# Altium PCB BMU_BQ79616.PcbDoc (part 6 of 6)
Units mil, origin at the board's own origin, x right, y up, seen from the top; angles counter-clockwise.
Board outline 7605 x 4005 mil, 4 copper layers (Top Layer, Layer 1, Layer 2, Bottom Layer), stack 37.446 mil thick; 709 components, 447 nets, 2028 pads, 1862 vias.
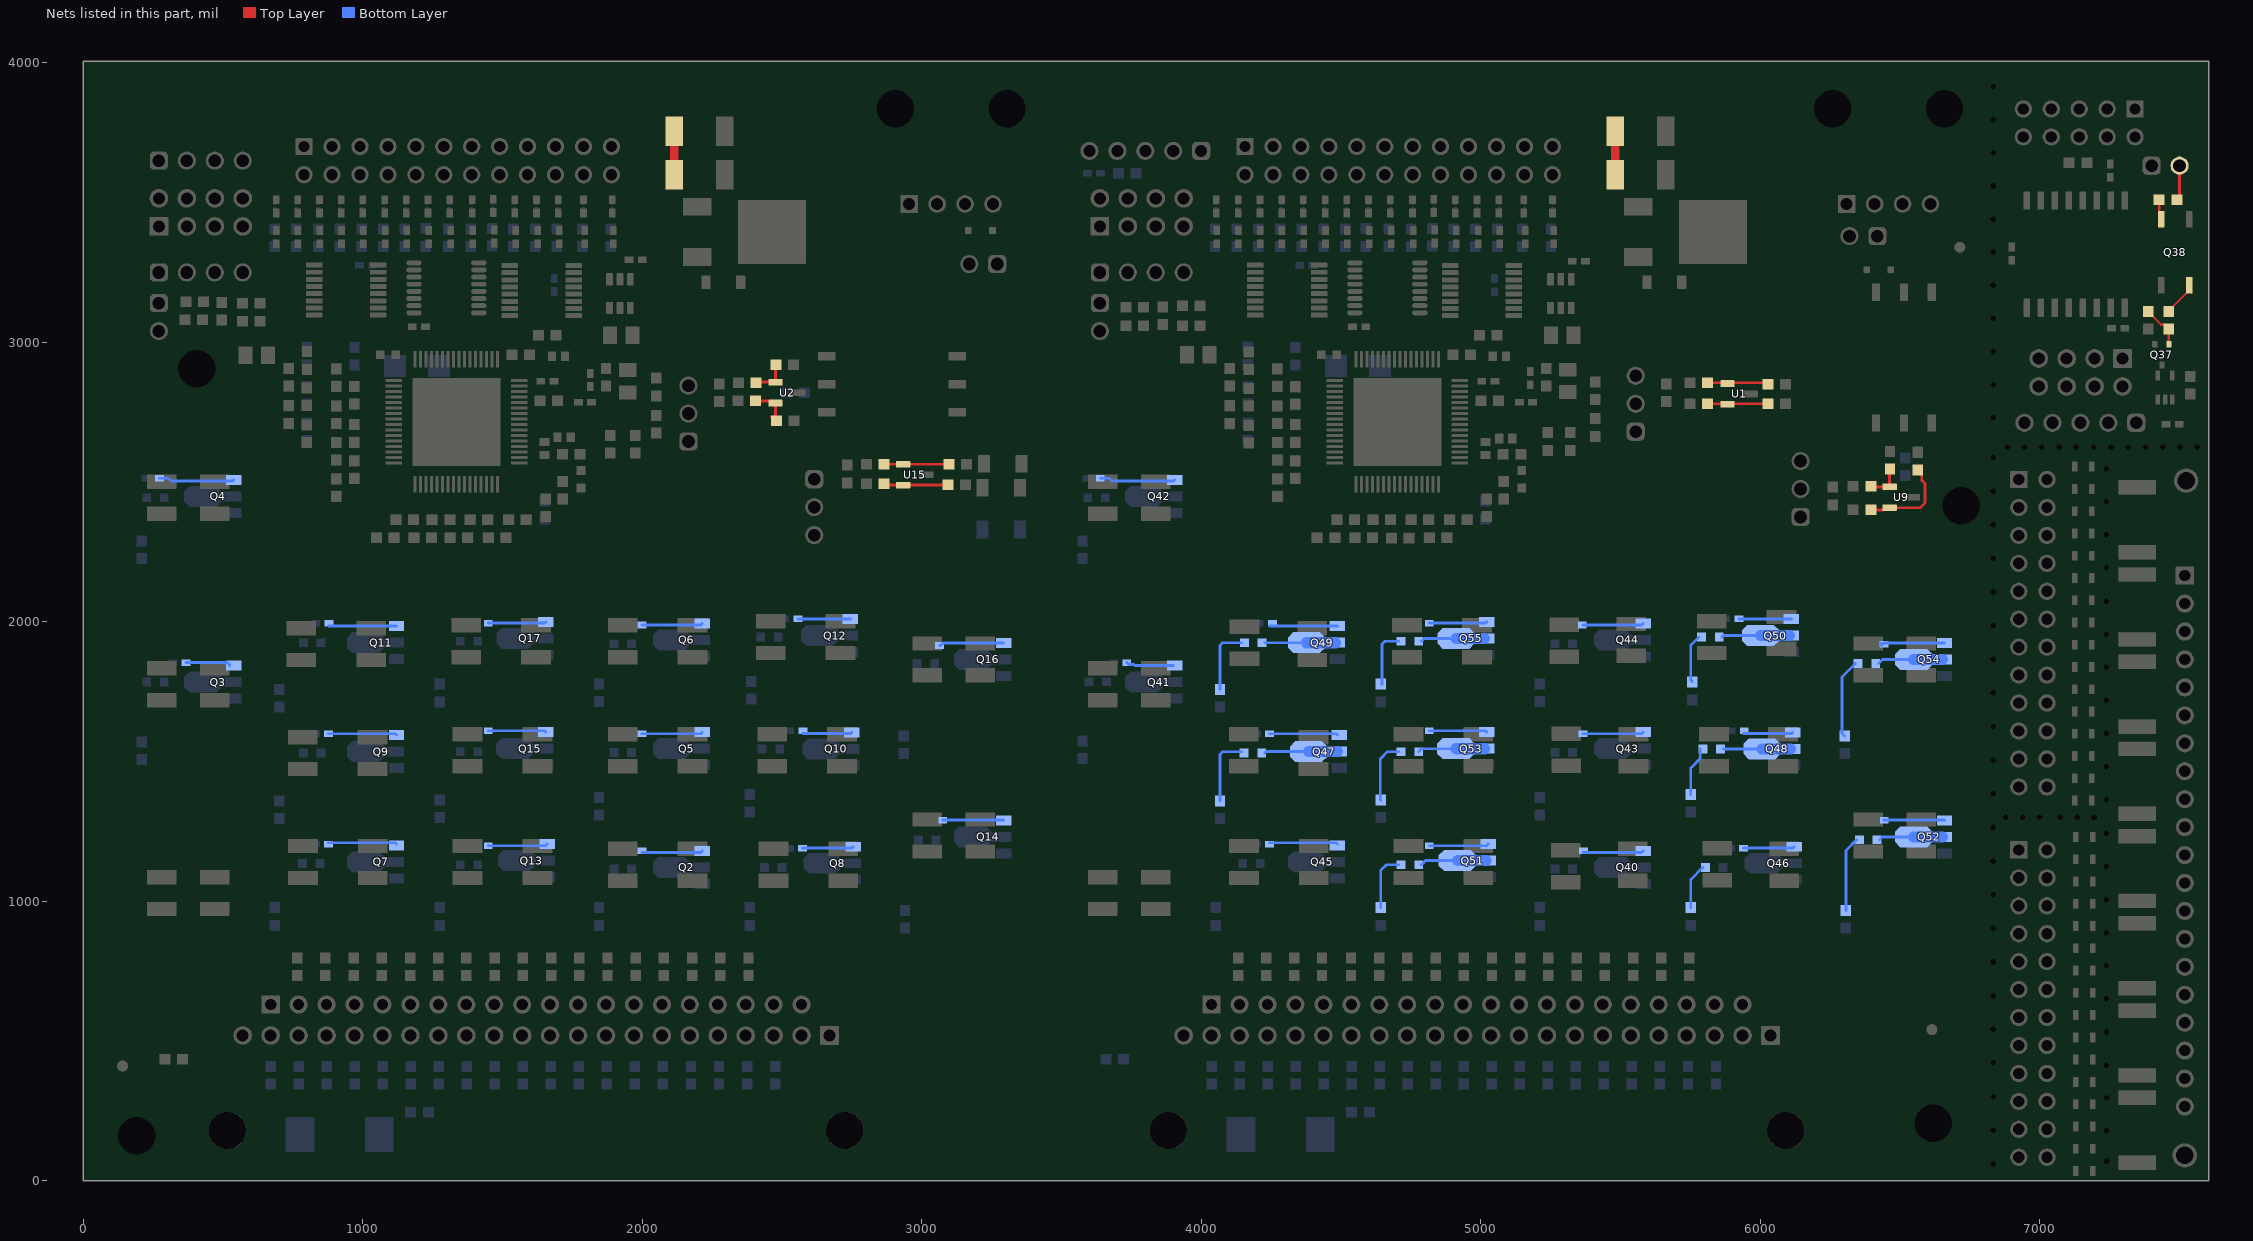
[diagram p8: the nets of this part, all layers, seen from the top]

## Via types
v1: diameter 20, hole 10, Top Layer to Bottom Layer, tented both sides, 1385 vias
v2: diameter 22.01, hole 12.01, Top Layer to Bottom Layer, tented both sides, 405 vias
v3: diameter 19.68, hole 7.87, Top Layer to Bottom Layer, 72 vias

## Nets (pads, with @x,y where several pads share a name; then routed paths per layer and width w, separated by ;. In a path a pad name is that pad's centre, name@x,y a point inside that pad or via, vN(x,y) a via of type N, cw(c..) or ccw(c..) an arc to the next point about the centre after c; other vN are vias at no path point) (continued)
NetD63_2: D63.2 R455.2 | length 161
  Bottom Layer w10: R455.2@5752.36,976.5 5752.36,1077.68 D63.2@5794.69,1120
NetD64_1: D64.1 Q47.2 Q47.4 | length 254.6
  Bottom Layer w10: D64.1@4227.36,1530 4232.76,1535.39 Q47.4@4377.36,1535.39
  Bottom Layer w40: Q47.4@4384.57,1535 Q47.2@4486.93,1535
NetD64_2: D64.2 R456.2 | length 248.5
  Bottom Layer w10: R456.2@4067.36,1357.99 4067.36,1525 4077.36,1535 D64.2@4144.69,1535
NetD65_1: D65.1 Q48.2 Q48.4 | length 240.6
  Bottom Layer w10: D65.1@5868.7,1545 Q48.4@6006.93,1545
  Bottom Layer w40: Q48.4@6006.93,1545 Q48.2@6109.29,1545
NetD65_2: D65.2 R465.2 | length 177.4
  Bottom Layer w10: R465.2@5752.36,1381.5 5752.36,1476.34 5786.02,1510 D65.2@5786.02,1545
NetD66_1: D66.1 Q49.2 Q49.4 | length 252.4
  Bottom Layer w10: D66.1@4227.36,1925 Q49.4@4377.36,1925
  Bottom Layer w40: Q49.4@4377.36,1925 Q49.2@4479.72,1925
NetD66_2: D66.2 R466.2 | length 238.5
  Bottom Layer w10: R466.2@4067.36,1757.99 4067.36,1915 4077.36,1925 D66.2@4144.69,1925
NetD67_1: D67.1 Q50.2 Q50.4 | length 242.9
  Bottom Layer w10: D67.1@5863.7,1945 5869.32,1950.62 Q50.4@6001.93,1950.62
  Bottom Layer w40: Q50.4@6001.93,1950.62 Q50.2@6104.29,1950.62
NetD67_2: D67.2 R475.2 | length 172.4
  Bottom Layer w10: R475.2@5757.36,1786.5 5752.36,1791.5 5752.36,1916.34 D67.2@5781.02,1945
NetD68_1: D68.1 Q51.2 Q51.4 | length 237.2
  Bottom Layer w10: D68.1@4788.42,1130 4803.82,1145.39 Q51.4@4916.93,1145.39
  Bottom Layer w40: Q51.4@4916.93,1145.39 Q51.2@5019.29,1145.39
NetD68_2: D68.2 R476.2 | length 205.2
  Bottom Layer w10: R476.2@4642.36,976.5 4642.36,1110 4662.36,1130 D68.2@4705.74,1130
NetD69_1: D69.1 Q52.2 Q52.4 | length 227.8
  Bottom Layer w10: D69.1@6428.7,1220 6438.7,1230 Q52.4@6550,1230
  Bottom Layer w40: Q52.4@6550,1230 Q52.2@6652.36,1230
NetD69_2: D69.2 R485.2 | length 269.5
  Bottom Layer w10: R485.2@6307.36,966.5 6307.43,966.56 6307.43,1181.4 D69.2@6346.02,1220
NetD70_1: D70.1 Q53.2 Q53.4 | length 239.7
  Bottom Layer w10: D70.1@4778.57,1535 4789.27,1545.69 Q53.4@4911.5,1545.69
  Bottom Layer w40: Q53.4@4911.5,1545.69 Q53.2@5013.86,1545.69
NetD70_2: D70.2 R486.2 | length 223.6
  Bottom Layer w10: R486.2@4642.36,1361.5 4640.74,1363.12 4640.74,1508.38 4667.36,1535 D70.2@4705.74,1535
NetD71_1: D71.1 Q54.2 Q54.4 | length 234.9
  Bottom Layer w10: D71.1@6423.7,1850 6438.7,1865 Q54.4@6550,1865
  Bottom Layer w40: Q54.4@6550,1865 Q54.2@6652.36,1865
NetD71_2: D71.2 R495.2 | length 281.9
  Bottom Layer w10: R495.2@6302.36,1591.5 6293.41,1600.44 6293.41,1802.39 D71.2@6341.02,1850
NetD72_1: D72.1 Q55.2 Q55.4 | length 230.2
  Bottom Layer w10: D72.1@4788.43,1930 4798.82,1940.39 Q55.4@4911.93,1940.39
  Bottom Layer w40: Q55.4@4911.93,1940.39 Q55.2@5014.29,1940.39
NetD72_2: D72.2 R496.2 | length 206
  Bottom Layer w10: R496.2@4647.36,1776.5 4647.36,1920 4657.36,1930 D72.2@4705.75,1930
NetJ5_2: J5.2 R142.1 | length 126
  Top Layer w8: J5.2@7501.24,3601.97 J5.2@7501.24,3631.97
  Top Layer w10: R142.1@7491.5,3510 7501.24,3519.74 J5.2@7501.24,3601.97
NetQ2_1: Q2.1 R12.2 | length 218.6
  Bottom Layer w10: R12.2@1998.62,1173.77 2208.9,1173.77 Q2.1@2214.8,1179.68
NetQ3_1: Q3.1 R13.2 | length 161.9
  Bottom Layer w10: R13.2@366.57,1853.75 515.19,1853.75 523.15,1845.8 Q3.1@523.15,1843.75
NetQ4_1: Q4.1 R16.2 | length 272
  Bottom Layer w10: R16.2@271.57,2513.75 302.95,2513.75 312.95,2503.75 533.7,2503.75 Q4.1@537.75,2507.81
NetQ5_1: Q5.1 R17.2 | length 218.6
  Bottom Layer w10: R17.2@1998.62,1598.77 2208.9,1598.77 Q5.1@2214.8,1604.68
NetQ6_1: Q6.1 R20.2 | length 218.6
  Bottom Layer w10: R20.2@1998.62,1988.15 2208.9,1988.15 Q6.1@2214.8,1994.06
NetQ7_1: Q7.1 R95.2 | length 244.6
  Bottom Layer w10: R95.2@877.4,1208.76 1115.92,1208.76 Q7.1@1120.24,1204.45
NetQ8_1: Q8.1 R106.2 | length 183.1
  Bottom Layer w10: R106.2@2573.62,1190 2750.13,1190 Q8.1@2754.8,1194.68
NetQ9_1: Q9.1 R107.2 | length 244.6
  Bottom Layer w10: R107.2@877.4,1598.76 1115.92,1598.76 Q9.1@1120.24,1594.45
NetQ10_1: Q10.1 R123.2 | length 177.9
  Bottom Layer w10: R123.2@2573.62,1600 2745.75,1600 Q10.1@2749.8,1604.06
NetQ11_1: Q11.1 R124.2 | length 243.2
  Bottom Layer w10: R124.2@877.4,1985 1119.29,1985 Q11.1@1120.24,1984.06
NetQ12_1: Q12.1 R134.2 | length 187.7
  Bottom Layer w10: R134.2@2557.24,2010 2744.48,2010 Q12.1@2744.8,2009.68
NetQ13_1: Q13.1 R135.2 | length 213.6
  Bottom Layer w10: R135.2@1448.62,1198.54 1653.9,1198.54 Q13.1@1659.8,1204.45
NetQ14_1: Q14.1 R136.2 | length 218.3
  Bottom Layer w10: R136.2@3075,1290 3291.93,1290 Q14.1@3292.87,1289.06
NetQ15_1: Q15.1 R137.2 | length 207.9
  Bottom Layer w10: R137.2@1448.62,1610 1649.12,1610 Q15.1@1654.37,1604.75
NetQ16_1: Q16.1 R138.2 | length 233
  Bottom Layer w10: R138.2@3063.62,1915 3067.56,1915 3076.61,1924.06 Q16.1@3292.87,1924.06
NetQ17_1: Q17.1 R139.2 | length 208
  Bottom Layer w10: R139.2@1448.62,1995 1650.35,1995 Q17.1@1654.8,1999.45
NetQ37_1: Q37.1 R140.2 R141.1 | length 152.6
  Top Layer w8: R140.2@7389.24,3110.46 7389.24,3109.48 7435.56,3063.16 7447.54,3063.16 7462.24,3048.46 R141.1@7462.24,3047.47 7462.83,3046.88 Q37.1@7462.83,2995.37
NetQ38_2: Q38.2 R142.2 | length 72.5
  Top Layer w10: R142.2@7428.5,3510 7428.5,3465.77 7435.95,3458.33 Q38.2@7435.95,3440.61
NetQ38_4: Q38.4 R141.2 | length 135.5
  Top Layer w8: R141.2@7462.24,3110.46 7476.94,3125.17 7476.94,3127.67 Q38.4@7535.95,3186.67 ; Q38.4@7535.95,3204.39 Q38.4@7535.95,3186.67 ; Q38.4@7543.76,3178.86 Q38.4@7535.95,3186.67
NetQ40_1: Q40.1 R427.2 | length 218.6
  Bottom Layer w10: R427.2@5365.98,1173.77 5576.26,1173.77 Q40.1@5582.17,1179.68
NetQ41_1: Q41.1 R428.2 | length 170.6
  Bottom Layer w10: R428.2@3733.93,1853.75 3740.26,1847.43 3758.98,1847.43 3762.66,1843.75 3899.56,1843.75 Q41.1@3900.11,1843.2
NetQ42_1: Q42.1 R437.2 | length 272
  Bottom Layer w10: R437.2@3638.93,2513.75 3670.31,2513.75 3680.31,2503.75 3901.06,2503.75 Q42.1@3905.11,2507.81
NetQ43_1: Q43.1 R438.2 | length 218.6
  Bottom Layer w10: R438.2@5365.98,1598.77 5576.26,1598.77 Q43.1@5582.17,1604.68
NetQ44_1: Q44.1 R447.2 | length 218.6
  Bottom Layer w10: R447.2@5365.98,1988.15 5576.26,1988.15 Q44.1@5582.17,1994.06
NetQ45_1: Q45.1 R448.2 | length 244.6
  Bottom Layer w10: R448.2@4244.76,1208.76 4483.28,1208.76 Q45.1@4487.6,1204.45
NetQ46_1: Q46.1 R457.2 | length 183.1
  Bottom Layer w10: R457.2@5940.98,1190 6117.49,1190 Q46.1@6122.17,1194.68
NetQ47_1: Q47.1 R458.2 | length 244.6
  Bottom Layer w10: R458.2@4244.76,1598.76 4483.28,1598.76 Q47.1@4487.6,1594.45
NetQ48_1: Q48.1 R467.2 | length 177.9
  Bottom Layer w10: R467.2@5940.98,1600 6113.11,1600 Q48.1@6117.17,1604.06
NetQ49_1: Q49.1 R468.2 | length 243.2
  Bottom Layer w10: R468.2@4244.76,1985 4486.65,1985 Q49.1@4487.6,1984.06
NetQ50_1: Q50.1 R477.2 | length 187.7
  Bottom Layer w10: R477.2@5924.61,2010 6111.84,2010 Q50.1@6112.17,2009.68
NetQ51_1: Q51.1 R478.2 | length 213.6
  Bottom Layer w10: R478.2@4815.98,1198.54 5021.26,1198.54 Q51.1@5027.17,1204.45
NetQ52_1: Q52.1 R487.2 | length 218.3
  Bottom Layer w10: R487.2@6442.36,1290 6659.29,1290 Q52.1@6660.24,1289.06
NetQ53_1: Q53.1 R488.2 | length 207.9
  Bottom Layer w10: R488.2@4815.98,1610 5016.48,1610 Q53.1@5021.73,1604.75
NetQ54_1: Q54.1 R497.2 | length 233
  Bottom Layer w10: R497.2@6433.78,1922.76 R497.2@6437.72,1922.76 ; R497.2@6434.92,1915 6443.98,1924.06 Q54.1@6660.24,1924.06
NetQ55_1: Q55.1 R498.2 | length 208
  Bottom Layer w10: R498.2@4815.98,1995 5017.72,1995 Q55.1@5022.17,1999.45
NetR24_2: R24.2 R25.1 | length 145
  Top Layer w30: R24.2@2114.45,3600 R25.1@2114.45,3745
NetR69_1: R69.1 R70.2 U15.2 | length 231.1
  Top Layer w10: R69.1@2864.84,2493.7 2869.65,2488.9 U15.2@2933.35,2488.9 3092.4,2488.9 R70.2@3093.5,2490
NetR71_1: R71.1 R72.2 U1.1 | length 219.1
  Top Layer w10: R72.2@5811.5,2855 6023.5,2855 R71.1@6028.5,2850
NetR75_1: R75.1 R76.2 U15.1 | length 232
  Top Layer w10: R75.1@2864.84,2563.7 U15.1@2933.35,2563.7 R76.2@3096.85,2563.7
NetR77_1: R77.1 R78.2 U1.2 | length 217
  Top Layer w10: R78.2@5811.5,2780 R77.1@6028.5,2780
NetR80_2: R80.2 R81.1 U9.1 | length 153.8
  Top Layer w10: R81.1@6410.2,2498.7 R81.1@6396.5,2485 6399.09,2482.4 U9.1@6463.66,2482.4 6463.66,2545.67 R80.2@6465,2547.01 R80.2@6465,2546.02
NetR82_2: R82.2 R83.1 U2.1 | length 135.5
  Top Layer w10: R82.2@2407.48,2855 R82.2@2406.5,2855 2408.9,2857.4 U2.1@2476.57,2857.4 2476.57,2918.07 R83.1@2478.5,2920
NetR88_2: R88.2 R89.1 U9.2 | length 332.7
  Top Layer w10: R89.1@6396.5,2400 6442.28,2400 6449.88,2407.6 U9.2@6463.66,2407.6 6572.6,2407.6 6590,2425 6590,2495 6578.7,2506.3 6578.7,2529.8 R88.2@6565,2543.5
NetR90_2: R90.2 R91.1 U2.2 | length 157.8
  Top Layer w10: R90.2@2404.68,2790 2405.67,2790 2455.39,2790 2462.8,2782.6 U2.2@2476.57,2782.6 R91.1@2476.57,2723.43 ; R91.1@2461.97,2733.7 2466.3,2733.7 R91.1@2476.57,2723.43 ; R91.1@2480,2720 R91.1@2476.57,2723.43
NetR151_2: R151.2 R152.1 | length 145
  Top Layer w30: R151.2@5481.81,3600 R152.1@5481.81,3745
pads on no net: FID1.1 FID2.1 FID3.1 FID4.1 FID5.1 FID6.1 J4.20 J10. J10.1 J10.2 J10.22 J12.1 J12.2 J12.4 J12.9 J12.10 J15.20 J18.20 J21. J21.1 J21.2 J21.22 J30.3 J30.4 J30.MH1 J30.MH2 J31.1 J31.2 J31.MH1 J31.MH2 LBL1.0 T1.5 T2.2 U3.4 U3.5 U7.7 U8.7 U17.14 U18.4 U18.5 U22.7 U23.7

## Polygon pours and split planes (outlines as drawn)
A1_GND on Top Layer "A1_GND_L01_P008" (solid, remove dead copper, pour order 8): 3435,3994.98 3435,-10 6810,-10 6810,3989.86
A2_GND on Top Layer "A2_GND_L01_P031" (solid, remove dead copper, pour order 31): 1.94,4005 1.94,0 3391.94,0 3391.94,3999.86
A2_GND on Top Layer "A2_GND_L01_P000" (solid, remove dead copper, pour order 0): 0,4005 0,0 3390,0 3390,3999.86
A1_GND_ISO on Top Layer "A1_GND_ISO_L01_P012" (solid, remove dead copper, pour order 12): 6865,4000 6865,3485 6885,3485 6980,3485 7605,3485 7605,4000
A0_GND on Top Layer "A0_GND_L01_P013" (solid, remove dead copper, pour order 13): 6860,3160 6860,2645 6880,2645 6975,2645 7600,2645 7600,3160
NetC3_2 on Top Layer "NETC3_2_L01_P020" (solid, remove dead copper, pour order 20): 2246.75,3064.24 2744.24,3064.24 2745,3065 2744.28,3065.72 2744.28,3854.96 2253.5,3854.96
NetC154_2 on Top Layer "NETC154_2_L01_P029" (solid, remove dead copper, pour order 29): 5616.08,3064.24 6113.57,3064.24 6114.33,3065 6113.61,3065.72 6113.61,3854.96 5622.83,3854.96
A2_GND on Layer 2 "A2_GND_L03_P006" (solid, remove dead copper, pour order 6): 0,4005 0,0 3365,0 3365,3999.89
A1_GND on Layer 2 "A1_GND_L03_P010" (solid, remove dead copper, pour order 10): 3435,3994.98 3435,-10 6810,-10 6810,3989.86
A0_GND on Layer 2 "A0_GND_L03_P015" (solid, pour order 15): 6860,3160 6860,2645 6880,2645 6975,2645 7600,2645 7600,3160
A1_GND_ISO on Layer 2 "A1_GND_ISO_L03_P018" (solid, pour order 18): 6865,4000 6865,3485 6885,3485 6980,3485 7605,3485 7605,4000
NetC154_2 on Layer 2 "NETC154_2_L03_P023" (solid, pour order 23): 5616.08,3064.24 6113.57,3064.24 6114.33,3065 6113.61,3065.72 6113.61,3854.96 5622.83,3854.96
NetC3_2 on Layer 2 "NETC3_2_L03_P027" (solid, pour order 27): 2246.75,3064.24 2744.24,3064.24 2745,3065 2744.28,3065.72 2744.28,3854.96 2253.5,3854.96
A2_GND on Layer 1 "A2_GND_L02_P005" (solid, remove dead copper, pour order 5): 0,4005 0,0 3365,0 3365,3999.89
A1_GND on Layer 1 "A1_GND_L02_P009" (solid, remove dead copper, pour order 9): 3435,3994.98 3435,-10 6810,-10 6810,3989.86
A0_GND on Layer 1 "A0_GND_L02_P014" (solid, remove dead copper, pour order 14): 6860,3160 6860,2645 6880,2645 6975,2645 7600,2645 7600,3160
A1_GND_ISO on Layer 1 "A1_GND_ISO_L02_P017" (solid, remove dead copper, pour order 17): 6865,4000 6865,3485 6885,3485 6980,3485 7605,3485 7605,4000
NetC154_2 on Layer 1 "NETC154_2_L02_P024" (solid, remove dead copper, pour order 24): 5616.08,3064.24 6113.57,3064.24 6114.33,3065 6113.61,3065.72 6113.61,3854.96 5622.83,3854.96
NetC3_2 on Layer 1 "NETC3_2_L02_P026" (solid, remove dead copper, pour order 26): 2246.75,3064.24 2744.24,3064.24 2745,3065 2744.28,3065.72 2744.28,3854.96 2253.5,3854.96
A1M_CELL0S on Layer 1 "A1M_CELL0S_L02_P030" (solid, pour order 30): 6860,2625 6870,2615 6870,0 7605,0 7605,2625
A2_GND on Bottom Layer "A2_GND_L04_P007" (solid, remove dead copper, pour order 7): 0,4005 0,0 3390,0 3390,3999.86
A1_GND on Bottom Layer "A1_GND_L04_P011" (solid, remove dead copper, pour order 11): 3435,3994.98 3435,-10 6810,-10 6810,3989.86
A0_GND on Bottom Layer "A0_GND_L04_P016" (solid, remove dead copper, pour order 16): 6860,3160 6860,2645 6880,2645 6975,2645 7600,2645 7600,3160
A1_GND_ISO on Bottom Layer "A1_GND_ISO_L04_P019" (solid, remove dead copper, pour order 19): 6865,4000 6865,3485 6885,3485 6980,3485 7605,3485 7605,4000
NetC154_2 on Bottom Layer "NETC154_2_L04_P025" (solid, remove dead copper, pour order 25): 5616.08,3064.24 6113.57,3064.24 6114.33,3065 6113.61,3065.72 6113.61,3854.96 5622.83,3854.96
NetC3_2 on Bottom Layer "NETC3_2_L04_P028" (solid, remove dead copper, pour order 28): 2246.75,3064.24 2744.24,3064.24 2745,3065 2744.28,3065.72 2744.28,3854.96 2253.5,3854.96

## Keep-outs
Keep-Out Layer:
  text ".Layer_Name" at 577,-858.49 h60

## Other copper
Top Layer:
  pour cut-out: 2030,2680 2000,2710 2000,2735 1985,2735 1995,2725 1995,2710 2015,2690 2015,2515 2030,2515
  pour cut-out: 2550,2975 2165.21,2975 2005,2814.79 2005,2705 2075,2635 2305,2635 2615,2635 2615,2975
  pour cut-out: 4039.92,3532.17 5394.92,3532.17 5394.92,3028.78 4039.92,3028.78
  pour cut-out: 670,3536.69 2025,3536.69 2025,3033.31 670,3033.31
  pour cut-out: 2560,2655 2560,2275 3205.18,2275 3235,2317.6 3235,2655
  pour cut-out: 6865,3595 7600,3595 7600,3060 7605,3055 6860,3055
  pour cut-out: 1517.64,2898.18 1517.64,2525 1147.64,2525 1142.64,2530 1142.64,2898.18 1517.64,2898.18 1492.64,2875 1177.64,2875 1167.64,2865 1167.64,2540 1487.64,2540 1492.64,2545 1492.64,2875
  pour cut-out: 2260,3518.31 2035,3518.31 2035,3803.31 2260,3803.31
  pour cut-out: 115,3935 60,3880 60,95 105,50 215,50 215,3790 230,3805 2820,3805 2820,3935
  pour cut-out: 5605,3502.5 5380,3502.5 5380,3787.5 5605,3787.5
  pour cut-out: 75,2750.25 75,3017.5 1170,3017.5 1170,2547.88 1483.71,2547.88 1623.03,2408.56 1623.03,2364.25 1623.03,2270 831.59,2270 699.09,2402.5 699.09,2750.25
  region net A2_BAT: 980,2963.64 1047.64,2970 1047.64,2940 1012.26,2931.38 998.63,2945 980,2945
  region net A1_BAT: 4347.36,2963.64 4415,2970 4415,2940 4379.62,2931.38 4366,2945 4347.36,2945
  pour cut-out: 3410,2740.9 3410,3008.15 4547.87,3008.15 4547.87,2538.53 4861.58,2538.53 5000.9,2399.21 5000.9,2354.9 5000.9,2260.65 4209.46,2260.65 4076.96,2393.15 4076.96,2740.9
  pour cut-out: 3574.98,385.01 3580,379.99 3580,0 3420,0 3422.89,2.89 3422.89,363.21
  pour cut-out: 5975,2965 5925,2965 5485,2965 5480,2960 5450,2960 5437.2,2947.2 5437.2,2637.8 5450,2625 5680,2625 6170,2625 6170,2965
  pour cut-out: 3540,3815 3495,3770 3495,2495 3420,2420 3300,2420 3300,2625 3295,2630 3320,2655 3335,2655 3335,3790 3355,3810 3355,3850 3410,3905 3425,3905
  pour cut-out: 3425,3940 6195,3940 6195,3790 3425,3790 3425,3860
  pour cut-out: 4885,2898.18 4885,2525 4515,2525 4510,2530 4510,2898.18 4885,2898.18 4860,2875 4545,2875 4535,2865 4535,2540 4855,2540 4860,2545 4860,2875
  pour cut-out: 197.71,820 2780,820 2780,345.87 193.2,345.87
  pour cut-out: 3427.33,830 6148.85,830 6148.85,363.21 3422.89,363.21
  region net A1_CB15: 3549.43,2110 3549.43,1788.41 3949.43,1788.41 3949.43,2110
  pour cut-out: 6600,2655 6550,2655 6110,2655 6105,2650 6095,2650 6095,2315 6305,2315 6825,2315 6825,2655
  pour cut-out: 5210,2554.18 5223.29,2554.18 5223.29,2476.71 5305,2395 6091.63,2395 6095,2398.37 6095,2385 5300,2385 5210,2475
  pour cut-out: 5380,2625 5390,2625 5390,2535 5405,2520 6095,2520 6090,2515 6090,2510 5395,2510 5380,2525
  pour cut-out: 1995,2400 1920,2400 1885,2435 1885,2560 1855,2560 1840,2560 1840,2550 1875,2550 1875,2430 1915,2390 1995,2390
  pour cut-out: 1995,2390 2555,2390 2635,2390 2635,2400 1995,2400
  pour cut-out: 2015,2505 2550,2505 2555,2505 2625,2570 2630,2570 2630,2585 2625,2590 2550,2515 2015,2515
  region net A2_CB14: 182.07,2750 182.07,2463.41 582.07,2463.41 582.07,2750
  region net A1_CB14: 3549.43,2750 3549.43,2463.41 3949.43,2463.41 3949.43,2750
  region net A1_CB4: 5722.36,1326.39 5722.36,1146.39 6210.68,1146.39 6210.68,1326.39
  region net A1_CB7: 5167.36,1325 5167.36,1145 5647.36,1145 5647.36,1325
  region net A1_CELL4: 5722.36,1120.8 5722.36,940.8 6212.44,940.8 6212.44,1120.8
  region net A1_CELL3: 5727.36,1532.05 5727.36,1352.05 6208.28,1352.05 6208.28,1532.05
  region net A1_CELL6: 5172.36,1530.66 5172.36,1350.66 5649.97,1350.66 5649.97,1530.66
  region net A1_CELL7: 5167.36,1119.4 5167.36,939.4 5649.12,939.4 5649.12,1119.4
  region net A1_CELL10: 4589.12,1124.4 4589.12,944.4 5097.36,944.4 5097.36,1124.4
  region net A1_CB10: 4587.36,1330 4587.36,1150 5097.36,1150 5097.36,1330
  region net A1_CELL9: 4589.97,1525.66 4589.97,1345.66 5097.36,1345.66 5097.36,1525.66
  region net A1_CELL1: 6287.36,1218.1 6287.36,885 6690.63,885 6690.63,1218.1
  region net A1_CB1: 6292.36,1560 6292.36,1264.93 6692.36,1264.93 6692.36,1560
  region net A1_CB13: 4018.39,1325 4018.39,1145 4517.36,1145 4517.36,1325
  region net A1_CELL13: 4020.15,1119.4 4020.15,939.4 4517.36,939.4 4517.36,1119.4
  region net A1_CELL12: 4019.97,1515.66 4019.97,1335.66 4522.36,1335.66 4522.36,1515.66
  region net A1_CB2: 5717.36,2152.65 5717.36,1972.65 6206.53,1972.65 6206.53,2152.65
  region net A1_CB5: 5172.36,2136.25 5172.36,1956.25 5647.36,1956.25 5647.36,2136.25
  region net A1_CB0: 6282.36,2195 6282.36,1884.69 6692.26,1884.69 6692.26,2195
  region net A1_CELL0S: 6287.36,1837.86 6287.36,1572.79 6690.52,1572.79 6690.52,1837.86
  region net A1_CELL2: 5717.36,1947.05 5717.36,1767.05 6208.28,1767.05 6208.28,1947.05
  region net A1_CB3: 5717.36,1737.65 5717.36,1557.65 6206.53,1557.65 6206.53,1737.65
  region net A1_CELL14: 3549.43,2438.48 3549.43,2125 3949.43,2125 3949.43,2438.48
  region net A1_CB8: 4588.21,2131.25 4588.21,1951.25 5092.36,1951.25 5092.36,2131.25
  region net A1_CELL11: 4019.97,1915.66 4019.97,1735.66 4517.36,1735.66 4517.36,1915.66
  region net A1_CELL8: 4589.97,1925.66 4589.97,1745.66 5092.36,1745.66 5092.36,1925.66
  region net A1_CB12: 4018.21,1721.25 4018.21,1541.25 4522.36,1541.25 4522.36,1721.25
  region net A1_CB9: 4588.21,1731.25 4588.21,1551.25 5097.36,1551.25 5097.36,1731.25
  region net A1_CELL5: 5172.36,1930.66 5172.36,1750.66 5647.36,1750.66 5647.36,1930.66
  region net A1_CB6: 5172.36,1736.25 5172.36,1556.25 5648.21,1556.25 5648.21,1736.25
  region net A1_CB16: 3547.36,1405 3547.36,1033.68 3940.31,1033.68 3940.31,1405
  region net A1_CELL16S: 3547.36,1008.75 3547.36,655 3940.31,655 3940.31,1008.75
  region net A1_CELL15: 3549.43,1763.48 3549.43,1425 3949.43,1425 3949.43,1763.48
  region net A1_CB11: 4018.21,2121.25 4018.21,1941.25 4517.36,1941.25 4517.36,2121.25
  region net A2_CB5: 1805,2136.25 1805,1956.25 2280,1956.25 2280,2136.25
  region net A2_CELL5: 1805,1930.66 1805,1750.66 2280,1750.66 2280,1930.66
  region net A2_CB6: 1805,1736.25 1805,1556.25 2280.85,1556.25 2280.85,1736.25
  region net A2_CELL6: 1805,1530.66 1805,1350.66 2282.6,1350.66 2282.6,1530.66
  region net A2_CELL11: 652.6,1915.66 652.6,1735.66 1150,1735.66 1150,1915.66
  region net A2_CB11: 650.85,2121.25 650.85,1941.25 1150,1941.25 1150,2121.25
  region net A2_CELL2: 2350,1947.05 2350,1767.05 2840.92,1767.05 2840.92,1947.05
  region net A2_CB2: 2350,2152.65 2350,1972.65 2839.16,1972.65 2839.16,2152.65
  region net A2_CELL0S: 2920,1837.86 2920,1572.79 3323.16,1572.79 3323.16,1837.86
  region net A2_CELL4: 2355,1120.8 2355,940.8 2845.08,940.8 2845.08,1120.8
  region net A2_CB3: 2350,1737.65 2350,1557.65 2839.16,1557.65 2839.16,1737.65
  region net A2_CELL3: 2360,1532.05 2360,1352.05 2840.92,1352.05 2840.92,1532.05
  region net A2_CB4: 2355,1326.39 2355,1146.39 2843.32,1146.39 2843.32,1326.39
  region net A2_CELL10: 1221.76,1124.4 1221.76,944.4 1730,944.4 1730,1124.4
  region net A2_CELL9: 1222.6,1525.66 1222.6,1345.66 1730,1345.66 1730,1525.66
  region net A2_CB8: 1220.85,2131.25 1220.85,1951.25 1725,1951.25 1725,2131.25
  region net A2_CELL8: 1222.6,1925.66 1222.6,1745.66 1725,1745.66 1725,1925.66
  region net A2_CB9: 1220.85,1731.25 1220.85,1551.25 1730,1551.25 1730,1731.25
  region net A2_CB12: 650.85,1721.25 650.85,1541.25 1155,1541.25 1155,1721.25
  region net A2_CELL12: 652.6,1515.66 652.6,1335.66 1155,1335.66 1155,1515.66
  region net A2_CB13: 651.03,1325 651.03,1145 1150,1145 1150,1325
  region net A2_CB10: 1220,1330 1220,1150 1730,1150 1730,1330
  region net A2_CELL13: 653.01,1095.63 653.01,915.63 1150.22,915.63 1150.22,1095.63
  region net A2_CB7: 1800,1325 1800,1145 2280,1145 2280,1325
  region net A2_CELL7: 1800,1119.4 1800,939.4 2281.76,939.4 2281.76,1119.4
  region net A2_CELL15: 182.07,1763.48 182.07,1425 582.07,1425 582.07,1763.48
  region net A2_CB15: 182.07,2110 182.07,1788.41 582.07,1788.41 582.07,2110
  region net A2_CELL16S: 180,1008.75 180,655 572.95,655 572.95,1008.75
  region net A2_CB16: 180,1405 180,1033.68 572.95,1033.68 572.95,1405
  region net A2_CELL14: 182.07,2438.48 182.07,2125 582.07,2125 582.07,2438.48
  region net A2_CB1: 2925,1560 2925,1264.93 3325,1264.93 3325,1560
  region net A2_CELL1: 2920,1218.1 2920,885 3323.26,885 3323.26,1218.1
  region net A2_CB0: 2915,2195 2915,1884.69 3324.9,1884.69 3324.9,2195
  region net A2_CB0: 2915,2195 2915,1884.69 3324.9,1884.69 3324.9,2195
  region net A2_CELL1: 2920,1218.1 2920,885 3323.26,885 3323.26,1218.1
  region net A2_CB1: 2925,1560 2925,1264.93 3325,1264.93 3325,1560
  region net A2_CELL14: 182.07,2438.48 182.07,2125 582.07,2125 582.07,2438.48
  region net A2_CB14: 182.07,2750 182.07,2463.41 582.07,2463.41 582.07,2750
  region net A2_CB16: 180,1405 180,1033.68 572.95,1033.68 572.95,1405
  region net A2_CELL16S: 180,1008.75 180,655 572.95,655 572.95,1008.75
  region net A2_CB15: 182.07,2110 182.07,1788.41 582.07,1788.41 582.07,2110
  region net A2_CELL15: 182.07,1763.48 182.07,1425 582.07,1425 582.07,1763.48
  region net A2_CELL7: 1800,1119.4 1800,939.4 2281.76,939.4 2281.76,1119.4
  region net A2_CB7: 1800,1325 1800,1145 2280,1145 2280,1325
  region net A2_CELL13: 652.79,1119.4 652.79,939.4 1150,939.4 1150,1119.4
  region net A2_CB10: 1220,1330 1220,1150 1730,1150 1730,1330
  region net A2_CB13: 651.03,1325 651.03,1145 1150,1145 1150,1325
  region net A2_CELL12: 652.6,1515.66 652.6,1335.66 1155,1335.66 1155,1515.66
  region net A2_CB12: 650.85,1721.25 650.85,1541.25 1155,1541.25 1155,1721.25
  region net A2_CB9: 1220.85,1731.25 1220.85,1551.25 1730,1551.25 1730,1731.25
  region net A2_CELL8: 1222.6,1925.66 1222.6,1745.66 1725,1745.66 1725,1925.66
  region net A2_CB8: 1220.85,2131.25 1220.85,1951.25 1725,1951.25 1725,2131.25
  region net A2_CELL9: 1222.6,1525.66 1222.6,1345.66 1730,1345.66 1730,1525.66
  region net A2_CELL10: 1221.76,1124.4 1221.76,944.4 1730,944.4 1730,1124.4
  region net A2_CB4: 2355,1326.39 2355,1146.39 2843.32,1146.39 2843.32,1326.39
  region net A2_CELL3: 2360,1532.05 2360,1352.05 2840.92,1352.05 2840.92,1532.05
  region net A2_CB3: 2350,1737.65 2350,1557.65 2839.16,1557.65 2839.16,1737.65
  region net A2_CELL4: 2355,1120.8 2355,940.8 2845.08,940.8 2845.08,1120.8
  region net A2_CELL0S: 2920,1837.86 2920,1572.79 3323.16,1572.79 3323.16,1837.86
  region net A2_CB2: 2350,2152.65 2350,1972.65 2839.16,1972.65 2839.16,2152.65
  region net A2_CELL2: 2350,1947.05 2350,1767.05 2840.92,1767.05 2840.92,1947.05
  region net A2_CB11: 650.85,2121.25 650.85,1941.25 1150,1941.25 1150,2121.25
  region net A2_CELL11: 652.6,1915.66 652.6,1735.66 1150,1735.66 1150,1915.66
  region net A2_CELL6: 1805,1530.66 1805,1350.66 2282.6,1350.66 2282.6,1530.66
  region net A2_CB6: 1805,1736.25 1805,1556.25 2280.85,1556.25 2280.85,1736.25
  region net A2_CELL5: 1805,1930.66 1805,1750.66 2280,1750.66 2280,1930.66
  region net A2_CB5: 1805,2136.25 1805,1956.25 2280,1956.25 2280,2136.25
  text ".Layer_Name" at 577,-858.49 h60
Layer 1:
  pour cut-out: 5347.36,2785 5337.36,2775 4882.36,2775 4882.36,2780 4912.36,2780 5329.76,2780 5347.36,2797.6
  pour cut-out: 5347.36,2797.6 5347.36,2785 5492.36,2930 5922.36,2930 6187.36,3195 6187.36,3940 5487.44,3940 5488.92,3005 4834.88,3005 4819.86,2989.99 4819.86,2890 4822.36,2890 4822.36,2945 4822.36,2981.91 4839.86,2997.5 5349.86,2997.5 5503.09,2997.5 5501.59,3925 6167.36,3925 6167.36,3200 5912.36,2945 5489.02,2945
  pour cut-out: 1980,2797.6 1980,2785 2125,2930 2555,2930 2820,3195 2820,3940 2120.07,3940 2121.56,3005 1467.51,3005 1452.5,2989.99 1452.5,2890 1455,2890 1455,2945 1455,2981.91 1472.5,2997.5 1982.5,2997.5 2135.72,2997.5 2134.22,3925 2800,3925 2800,3200 2545,2945 2121.66,2945
  pour cut-out: 4882.36,2700 5197.36,2700 5197.36,2615 5207.36,2605 5207.36,2390 5817.36,2390 5877.36,2330 6792.36,2330 6792.36,2315 5877.36,2315 5817.36,2375 5197.36,2375 5187.36,2385 5187.36,2685 5182.36,2690 4882.36,2690
  pour cut-out: 4882.36,2895.73 4882.36,2525 4515,2525 4510,2530 4510,2895.73 4882.36,2895.73 4860,2875 4545,2875 4535,2865 4535,2540 4855,2540 4860,2545 4860,2875
  pour cut-out: 5347.36,2785 5337.36,2775 4882.36,2775 4882.36,2780 4912.36,2780 5329.76,2780 5347.36,2797.6
  pour cut-out: 1515,2700 1830,2700 1830,2615 1840,2605 1840,2390 2450,2390 2480,2360 3010,2360 3425,2360 3425,2345 3010,2345 2480,2345 2450,2375 1830,2375 1820,2385 1820,2685 1815,2690 1515,2690
  pour cut-out: 1515,2895.73 1515,2525 1147.64,2525 1142.64,2530 1142.64,2895.73 1515,2895.73 1492.64,2875 1177.64,2875 1167.64,2865 1167.64,2540 1487.64,2540 1492.64,2545 1492.64,2875
  pour cut-out: 1980,2785 1970,2775 1515,2775 1515,2780 1545,2780 1962.4,2780 1980,2797.6
Bottom Layer:
  pour cut-out: 4038.34,3530.2 5393.34,3530.2 5393.34,3026.81 4038.34,3026.81
  pour cut-out: 670,3536.69 2025,3536.69 2025,3033.31 670,3033.31
  region net A1_GND: 3330,2360 3330,2390 3335,2395 3370,2395 3375,2390 3375,2360
  pour cut-out: 5720,3945 3420,3945 3420,40 4290,40 4290,365 3565,365 3565,3730 5720,3730
  pour cut-out: 3574.98,385.01 3580,379.99 3580,0 3420,0 3422.89,2.89 3422.89,363.21
  pour cut-out: 3572.36,2845 3572.36,2760 3967.36,2760 3982.36,2775 3987.36,2770 3987.36,2390 5013.82,2390 5018.83,2384.99 5022.36,2388.52 5022.36,2442.95 4463.27,2442.95 4438.62,2467.6 4440.39,2469.37 4440.39,2825.76 4543.13,2825.76 4557.36,2840 4554.13,2843.23 4554.13,2973.23 4522.36,3005 4515.84,2998.47 4419.2,2998.47 4375.88,3035 4335.22,3035 3582.36,3035 3572.36,3025
  pour cut-out: 205,2845 205,2760 600,2760 615,2775 620,2770 620,2390 1646.46,2390 1651.47,2384.99 1655,2388.52 1655,2442.95 1095.91,2442.95 1071.26,2467.6 1073.02,2469.37 1073.02,2825.76 1175.76,2825.76 1190,2840 1186.77,2843.23 1186.77,2973.23 1155,3005 1148.47,2998.47 1051.84,2998.47 1008.52,3035 967.86,3035 215,3035 205,3025
  region net A1_BAT: 4347.36,2963.63 4376,2935 4437.4,2935 4441.02,2936.3 4447.36,2937.72 4447.36,2955 4417.36,2955 4382.36,2990 4350,2990 4347.36,2975.81
  pour cut-out: 3540,713.21 6148.85,713.21 6148.85,363.21 3540,363.21
  pour cut-out: 198.15,713.21 2781.48,713.21 2781.48,363.21 194.82,363.21
  pour cut-out: 2700,3930 160,3930 60,3830 60,95 105,50 905,50 905,445 200,445 200,3775 230,3805 2640,3805 2700,3865
  region net A2_BAT: 980,2963.63 1008.63,2935 1070.04,2935 1073.66,2936.3 1080,2937.72 1080,2955 1050,2955 1015,2990 994.19,2990 980,2975.81
  region net A1_CB14: 3560.31,2745 3560.31,2538.75 3950.31,2538.75 3950.31,2745
  region net A1_CB2: 5747.36,2160 5747.36,2040 6227.36,2040 6227.36,2160
  region net A1_CB5: 5196.11,2145 5196.11,2025 5647.36,2025 5647.36,2145
  region net A1_CB11: 4052.36,2115 4052.36,2020 4518.61,2020 4518.61,2115
  region net A1_CELL14: 3615.31,2398.75 3615.31,2125 3950.31,2125 3950.31,2398.75
  region net A1_CB8: 4591.74,2135 4591.74,2035 5092.99,2035 5092.99,2135
  region net A1_CB7: 5247.36,1326.25 5247.36,1210 5632.36,1210 5632.36,1326.25
  region net A1_CB6: 5247.36,1737.5 5247.36,1635 5647.36,1635 5647.36,1737.5
  region net A1_CELL4: 5782.36,1075 5782.36,940 6182.36,940 6182.36,1075
  region net A1_CELL3: 5787.36,1485 5787.36,1350 6207.36,1350 6207.36,1485
  region net A1_CB4: 5782.36,1330 5782.36,1225 6182.36,1225 6182.36,1330
  region net A1_CELL1: 6337.36,1180 6337.36,885 6687.36,885 6687.36,1180
  region net A1_CELL7: 5247.36,1065 5247.36,937.81 5627.36,937.81 5627.36,1065
  region net A1_CELL11: 4099.86,1875 4099.86,1735 4512.36,1735 4512.36,1875
  region net A1_CB13: 4096.11,1325 4096.11,1230 4508.61,1230 4508.61,1325
  region net A1_CELL12: 4097.36,1480 4097.36,1337.5 4517.36,1337.5 4517.36,1480
  region net A1_CB12: 4101.11,1720 4101.11,1625 4513.61,1625 4513.61,1720
  region net A1_CB3: 5787.36,1740 5787.36,1635 6207.36,1635 6207.36,1740
  region net A1_CB1: 6342.36,1560 6342.36,1320 6687.36,1320 6687.36,1560
  region net A1_CELL0S: 6337.36,1805 6337.36,1575 6692.36,1575 6692.36,1805
  region net A1_CELL2: 5792.36,1895 5792.36,1770 6227.36,1770 6227.36,1895
  region net A1_CELL10: 4672.36,1095 4672.36,942.81 5052.36,942.81 5052.36,1095
  region net A1_CB10: 4677.36,1330 4677.36,1240 5062.36,1240 5062.36,1330
  region net A1_CELL13: 4083.61,1090 4083.61,937.5 4511.11,937.5 4511.11,1090
  region net A1_CB16: 3605.31,1400 3605.31,1033.75 3917.36,1033.75 3917.36,1400
  region net A1_CELL15: 3605.31,1728.75 3605.31,1425 3945.31,1425 3945.31,1728.75
  region net A1_CB15: 3609.86,2105 3609.86,1895 3944.86,1895 3944.86,2105
  region net A1_CELL8: 4677.36,1882.81 4677.36,1742.81 5103.17,1742.81 5103.17,1882.81
  region net A1_CB9: 4679.86,1727.5 4679.86,1632.5 5092.36,1632.5 5092.36,1727.5
  region net A1_CELL9: 4672.36,1490 4672.36,1342.81 5093.17,1342.81 5093.17,1490
  region net A1_CELL5: 5242.89,1875 5242.89,1750 5647.36,1750 5647.36,1875
  region net A1_CELL6: 5242.36,1495 5242.36,1347.81 5658.17,1347.81 5658.17,1495
  region net A1_CB0: 6287.36,2195 6287.36,1960 6692.36,1960 6692.36,2195
  region net A1_CELL16S: 3592.81,1008.75 3592.81,660 3915.31,660 3915.31,1008.75
  region net A2_CB16: 237.95,1400 237.95,1033.75 550,1033.75 550,1400
  region net A2_CB1: 2975,1560 2975,1320 3320,1320 3320,1560
  region net A2_CELL1: 2970,1180 2970,885 3320,885 3320,1180
  region net A2_CELL15: 237.95,1728.75 237.95,1425 577.95,1425 577.95,1728.75
  region net A2_CB14: 192.95,2745 192.95,2538.75 582.95,2538.75 582.95,2745
  region net A2_CELL14: 247.95,2398.75 247.95,2125 582.95,2125 582.95,2398.75
  region net A2_CELL16S: 225.45,1008.75 225.45,660 547.95,660 547.95,1008.75
  region net A2_CB15: 242.5,2105 242.5,1895 577.5,1895 577.5,2105
  region net A2_CELL0S: 2970,1805 2970,1575 3325,1575 3325,1805
  region net A2_CB0: 2920,2195 2920,1960 3325,1960 3325,2195
  region net A2_CELL4: 2415,1075 2415,940 2815,940 2815,1075
  region net A2_CB4: 2415,1330 2415,1225 2815,1225 2815,1330
  region net A2_CB3: 2420,1740 2420,1635 2840,1635 2840,1740
  region net A2_CELL3: 2420,1485 2420,1350 2840,1350 2840,1485
  region net A2_CELL2: 2425,1895 2425,1770 2860,1770 2860,1895
  region net A2_CB2: 2380,2160 2380,2040 2860,2040 2860,2160
  region net A2_CELL5: 1875.53,1875 1875.53,1750 2280,1750 2280,1875
  region net A2_CELL6: 1875,1495 1875,1347.81 2290.81,1347.81 2290.81,1495
  region net A2_CB6: 1880,1737.5 1880,1635 2280,1635 2280,1737.5
  region net A2_CELL7: 1880,1065 1880,937.81 2260,937.81 2260,1065
  region net A2_CB7: 1880,1326.25 1880,1210 2265,1210 2265,1326.25
  region net A2_CELL10: 1305,1095 1305,942.81 1685,942.81 1685,1095
  region net A2_CB10: 1310,1330 1310,1240 1695,1240 1695,1330
  region net A2_CELL9: 1305,1490 1305,1342.81 1725.81,1342.81 1725.81,1490
  region net A2_CB9: 1312.5,1727.5 1312.5,1632.5 1725,1632.5 1725,1727.5
  region net A2_CB5: 1828.75,2145 1828.75,2025 2280,2025 2280,2145
  region net A2_CB8: 1224.37,2135 1224.38,2035 1725.62,2035 1725.62,2135
  region net A2_CELL8: 1310,1882.81 1310,1742.81 1735.81,1742.81 1735.81,1882.81
  region net A2_CB11: 685,2115 685,2020 1151.25,2020 1151.25,2115
  region net A2_CELL13: 716.25,1090 716.25,937.5 1143.75,937.5 1143.75,1090
  region net A2_CB13: 728.75,1325 728.75,1230 1141.25,1230 1141.25,1325
  region net A2_CELL12: 730,1480 730,1337.5 1150,1337.5 1150,1480
  region net A2_CB12: 733.75,1720 733.75,1625 1146.25,1625 1146.25,1720
  region net A2_CELL11: 732.5,1875 732.5,1735 1145,1735 1145,1875
  text ".Layer_Name" at 577,-858.49 h60
Multi-Layer:
  pour cut-out: 3200,2651.51 3200,2275 3425,2275 3425,2730
  pour cut-out: 2605,2980 2605,2655 3350,2655 3425,2730 3425,4005 2820,4005 2820,3195
  pour cut-out: 2277.11,3064.24 2559.24,3064.24 2697.64,3202.64 2697.64,3765 2657.64,3805 2405,3805 2370,3770 2370,3655 2290.71,3655 2290.71,3545 2292.8,3542.91 2290,3540.12 2290,2965 2235,2965 2235,3520 2235,3854.96 2744.28,3854.96 2744.28,3179.28 2530,2965 2277.11,2965
  pour cut-out: 5650,3064.24 5926.6,3064.24 6065,3202.64 6065,3765 6025,3805 5772.36,3805 5737.36,3770 5737.36,3655 5658.07,3655 5658.07,3545 5660.16,3542.91 5657.36,3540.12 5657.36,2965 5602.36,2965 5602.36,3520 5602.36,3854.96 6111.64,3854.96 6111.64,3179.28 5897.36,2965 5650,2965
  pour cut-out: 6170,2660 6825,2660 6825,4010 6170,4010 6170,3440

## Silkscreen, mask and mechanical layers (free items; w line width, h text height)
Top Overlay:
  lines w10: 2005,2900 2220,3115 2685,3115 ; 5365,2950 5455,2950 5652.5,3147.5 5937.5,3147.5 ; 2685,3080 2685,3390 3010,3390 3030,3370 3030,3265 3070,3225 3070,3060 3060,3050 2715,3050 2685,3080 ; 5915,3170 5915,3258.39 6300,3258.39 6300,2905 6290,2895 6015,2895 5980,2930 5980,3105 5915,3170
  text "0/2/G/4/6/G/8/10/G/12/14/G / 1/3/G/5/7/G/9/11/G/13/15/G" at 5360,3845 h30
  text "0/2/G/4/6/G/8/10/G/12/14/G / 1/3/G/5/7/G/9/11/G/13/15/G" at 1840,3840 h30
  text "G/FLT/TX/RX/CVDD / G2/G4/G6/G8 / G1/G3/G5/G7 / TR2/TR1/TR0/T" at 3585,3750 h30
  text "CVDD/T/G8/G / G2/G4/G6/G8 / G1/G3/G5/G7 / TR2/TR1/TR0/T" at 190,3715 h30
  text "MCU_EN" at 7600,3505 h30 r90
  text "LN/LP" at 6505,3370 h30
  text "BN/BP" at 3520,3180 h30 r270
  text "HP/HN" at 3150,3170 h30
  text "BN/BP" at 155,3150 h30 r270
  text "HP/HN/G" at 2270,2735 h30 r270
  text "HP/HN/G" at 5535,2735 h30 r270
  text "G/LN/LP" at 6187.48,2580 h30 r270
  text "LN/LP/G" at 2656.81,2533.09 h30 r270
  text "16/16/15" at 7515,2380 h20 r270
  text "TOP/16S/15/--/1/0S/NA" at 5885,705 h30
  text "TOP/16S/15/--/1/0S/NA" at 2660,605 h30
  text "NA/0/0/1" at 7465,250 h20 r90
  text ".Layer_Name" at 577,-858.49 h60
Bottom Overlay:
  text "NA/TX/IG/FLT/NA / NA/RX/33/NA/NA" at 6920,3905 h30
  text "FLT/TX/RX/CVDD" at 6945,2985 h30
  text "G/FLT/TX/RX/CVDD" at 6895,2755 h30
  text "1/3/G/5/7/G/9/11/G/13/15/G / 0/2/G/4/6/G/8/10/G/12/14/G" at 7090,2260 h30 r270
  text "1/3/G/5/7/G/9/11/G/13/15/G / 0/2/G/4/6/G/8/10/G/12/14/G" at 7090,1190 h30 r270
  text ".Layer_Name" at 577,-858.49 h60
Top Paste:
  text ".Layer_Name" at 577,-858.49 h60
Bottom Paste:
  text ".Layer_Name" at 577,-858.49 h60
Top Solder:
  text ".Layer_Name" at 577,-858.49 h60
  text ".Layer_Name" at 577,-858.49 h60
Bottom Solder:
  text ".Layer_Name" at 577,-858.49 h60
Drill Guide:
  text ".Layer_Name" at 577,-858.49 h60
Mechanical 1:
  lines w10: 0,0 7605,0 7605,4010 0,4010 0,0
  text ".Layer_Name" at 577,-858.49 h60
Top 3D Body:
  rectangle: 125,-400 500,-275
  rectangle: 0,-275 125,-150
  lines w7: 0,-275 1000,-275 ; 125,-400 125,-150 ; 250,-400 250,-150 ; 500,-400 500,-150 ; 750,-400 750,-150 ; 0,-400 0,-150 1000,-150 1000,-400 0,-400
  text ".Layer_Name" at 577,-858.49 h60
Mechanical 3:
  text ".Layer_Name" at 577,-858.49 h60
Top Courtyard:
  text ".Layer_Name" at 577,-858.49 h60
Mechanical 5:
  lines w10: -292,-930.17 6308,-930.17 ; -292,-726.83 6310,-726.83 ; -292,-523.5 -292,-1133.5 3713,-1133.5 6310,-1133.5 6310,-523.5 -291.5,-523.5 -291.5,-1133.5 1284,-1133.5 ; 2173,-1133.5 2173,-523.5 ; 3440,-726.83 3440,-523.5 ; 4280,-726.83 4280,-523.5 ; 4902,-1140 4902,-937.17
  text "COMPONENTS MARKED 'DNP' SHOULD NOT BE POPULATED." at 1153.5,-318.5 h60
  text "ASSEMBLY VARIANT:" at 1153,-434 h60
  text ".VariantName" at 2189,-434 h60
  text "PCB VIEWED FROM TOP SIDE" at -228.5,-655.67 h60
  text "BOARD #:" at 2248,-655.67 h60
  text ".PRJ_Number" at 2793.5,-655.67 h60
  text "REV:" at 3638,-655.67 h60
  text ".PCB_Rev" at 3929.5,-655.67 h60
  text "SVN REV:" at 4476,-655.67 h60
  text ".VersionControl_RevNumber" at 4982,-655.67 h60
  text "TID #:" at 2248,-859 h60
  text ".TID" at 2793.5,-859 h60
  text "PLOT NAME =" at -228.5,-1064.34 h60
  text ".plot_File_Name" at 577,-1064.34 h60
  text "GENERATED    :" at 2250,-1064.34 h60
  text ".Print_Date" at 3119.5,-1064.34 h60
  text ".Print_Time" at 3848.5,-1064.34 h60
  text "TEXAS INSTRUMENTS" at 5113,-1064.34 h60
Top Assembly:
  lines w10: -292.5,-727.33 6309.5,-727.33 ; -290.5,-930.67 6309.5,-930.67 ; 1115.5,-1140.5 1115.5,-937.67 ; 1737.5,-727.33 1737.5,-524 ; 2577.5,-727.33 2577.5,-524 ; 3844.5,-1134 3844.5,-524 ; 4733.5,-1134 6309,-1134 6309,-524 -292.5,-524 -292.5,-1134 2304.5,-1134 6309.5,-1134 6309.5,-524
  text "COMPONENTS MARKED 'DNP' SHOULD NOT BE POPULATED." at 6102,-318 h60
  text ".VariantName" at 5058,-434 h60
  text "ASSEMBLY VARIANT:" at 6097,-434 h60
  text ".VersionControl_RevNumber" at 1035.5,-656.17 h60
  text "SVN REV:" at 1541.5,-656.17 h60
  text ".PCB_Rev" at 2088,-656.17 h60
  text "REV:" at 2379.5,-656.17 h60
  text ".PRJ_Number" at 3224,-656.17 h60
  text "BOARD #:" at 3769.5,-656.17 h60
  text "PCB VIEWED FROM BOTTOM SIDE" at 6246,-656.17 h60
  text ".TID" at 3224,-859.5 h60
  text "TID #:" at 3769.5,-859.5 h60
  text "TEXAS INSTRUMENTS" at 904.5,-1064.84 h60
  text ".Print_Time" at 2169,-1064.84 h60
  text ".Print_Date" at 2898,-1064.84 h60
  text "GENERATED    :" at 3767.5,-1064.84 h60
  text ".plot_File_Name" at 5440.5,-1064.84 h60
  text "PLOT NAME =" at 6246,-1064.84 h60
Mechanical 9:
  drawing of 57 lines, arcs and shapes, not listed
  text "1" at 739.84,8036.5 h70
  text "2" at 3235.5,8036.5 h70
  text "3" at 5724.84,8036.5 h70
  text "4" at 8231.51,8036.5 h70
  text "5" at 10730.5,8036.5 h70
  text "6" at 13235.5,8036.5 h70
  text "A" at -416.5,6893.5 h70
  text "A" at 14383.5,6893.5 h70
  text "B" at -416.5,4513.5 h70
  text "B" at 14383.5,4513.5 h70
  text "C" at -416.5,2138.5 h70
  text "C" at 14383.5,2138.5 h70
  text "PROJECT TITLE:" at 11343.5,277.5 h45
  text ".PRJ_Title" at 11393.5,144.17 h70
  text "DESIGNED FOR:" at 11343.5,-23.5 h45
  text ".PRJ_Customer" at 11393.5,-163.5 h70
  text "D" at -416.5,-231.5 h70
  text "D" at 14383.5,-231.5 h70
  text "FILE NAME:" at 11343.5,-323.5 h45
  text ".PCB_File_Name_No_Path" at 11393.5,-443.5 h70
  text "Texas Instruments (TI) and/or its licensors do not warrant the accuracy or completeness of this specification" at 6374,-605.34 h45
  text "ENGINEER:" at 11343.5,-613.5 h45
  text "LAYOUT BY:" at 12848.5,-613.5 h45
  text "or any information contained therein. TI and/or its licensors do not warrant that this design will meet" at 6329.01,-718 h45
  text ".PRJ_Engineer" at 11393.5,-768.49 h70
  text ".PCB_Layout" at 12899,-768.49 h70
  text "the specifications, will be suitable for your application or fit for any particular purpose, or will operate in" at 6329.01,-830.67 h45
  text ".Layer_Name" at 577,-858.49 h60
  text "ALTIUM DESIGNER VERSION:" at 12848.5,-923.5 h45
  text "an implementation. TI and/or its licensors do not warrant that the design is production worthy. You should" at 6329.01,-943.33 h45
  text "completely validate and test your design implementation to confirm the system functionality for your application." at 6374,-1056 h45
  text ".print_Scale" at 11393.5,-1056.83 h70
  text ".Application_BuildNumber" at 12899,-1056.83 h70
  text "1" at 739.84,-1263.5 h70
  text "2" at 3235.5,-1263.5 h70
  text "3" at 5724.84,-1263.5 h70
  text "5" at 10730.5,-1263.5 h70
  text "6" at 13235.5,-1263.5 h70
Mechanical 10:
  drawing of 189 lines, arcs and shapes, not listed
  text "DESIGN INFORMATION" at 12382.02,6356.17 h60
  text "MIN. TRACK WIDTH:" at 11737.46,6224.05 h60
  text "8" at 12833.7,6224.05 h60
  text "MIL" at 12988.46,6224.05 h60
  text "MIN. CLEARANCE:" at 11737.46,6099.92 h60
  text "0.2" at 12773.7,6099.93 h60
  text "mm" at 12988.46,6099.92 h60
  text "MIN. VIA PAD SIZE:" at 11737.46,5975.8 h60
  text "24" at 12803.71,5975.8 h60
  text "MIL" at 12988.46,5975.8 h60
  text "0.05mm (2MIL)" at 12432.46,5845.9 h60
  text "MINIMUM ANNULAR RING" at 11408.23,5837.67 h60
  text "EXTERNAL" at 13140.46,5837.67 h60
  text "PER" at 11608.23,5727.55 h60
  text "IPC-D-275 CLASS 2 LEVEL C" at 11828.23,5727.54 h60
  text "MIL, HOLES" at 13316.46,5627.07 h60
  text "+/-" at 12924,5618.48 h60
  text "+/-" at 13778,5618.48 h60
  text "REGISTRATION TOLERANCES:" at 11408.23,5617.42 h60
  text "METAL" at 12608,5617.42 h60
  text "5" at 13184.2,5617.42 h60
  text "3" at 14017.2,5617.42 h60
  text "MIL" at 14133.46,5617.42 h60
  text "HOLE SIZE TOLERANCE (UNLESS OTHERWISE SPECIFIED):" at 11408.23,5519.1 h60
  text "+/-" at 13778,5516.23 h60
  text "3" at 14017.2,5515.17 h60
  text "MIL" at 14133.46,5515.17 h60
  text "MATERIAL:" at 11333.46,5377.52 h60
  text "FR-4 High Tg" at 12319.9,5249 h60
  text "X" at 12175.46,5241.01 h60
  text "FR-408" at 11754.46,5236.49 h60
  text "OTHER" at 13242.46,5236.49 h60
  text "62 MIL (1.6mm) +/-10%" at 12074.56,5093.46 h60
  text "X" at 11954.46,5091.01 h60
  text "THICKNESS:" at 11408.23,5085.24 h60
  text "OTHER" at 13359.46,5085.24 h60
  text "TOLERANCE:" at 11408.23,4946.92 h60
  text "X" at 12256.46,4946.92 h60
  text "ANSI IPC-6012 TYPE 3 CLASS 2" at 12434.48,4946.92 h60
  text "OTHER +/-" at 12434.46,4802.73 h60
  text "BOW & TWIST:" at 11408.23,4657.54 h60
  text "X" at 12256.46,4657.54 h60
  text "ANSI IPC-6012 TYPE 3 CLASS 2" at 12434.48,4657.54 h60
  text "OTHER +/-" at 12434.46,4510.85 h60
  text "DRILLING:" at 11333.46,4380.23 h60
  text "NC_DRILL FILES" at 13094.46,4275.04 h60
  text "REFERENCE:" at 11408.23,4271.1 h60
  text "X" at 12065.46,4271.01 h60
  text "AS SHOWN" at 12243.46,4271.1 h60
  text "X" at 12966.46,4271.1 h60
  text "OTHER" at 13392.46,4128.85 h60
  text "PTH COPPER THICKNESS:" at 11407.91,4125.32 h60
  text "X" at 12547.14,4125.32 h60
  text "20-30 um" at 12675.14,4125.32 h60
  text "BOARD FINISH:" at 11333.46,3977.73 h60
  text "SILKSCREEN:" at 11488.68,3867.6 h60
  text "X" at 12446.46,3867.6 h60
  text "TOP" at 12563.46,3867.6 h60
  text "X" at 12956.46,3867.6 h60
  text "BOTTOM" at 13074.46,3867.6 h60
  text "SILKSCREEN COLOR:" at 11488.68,3712.41 h60
  text "X" at 12445.46,3712.41 h60
  text "WHITE" at 12563.46,3712.41 h60
  text "OTHER" at 13074.46,3712.41 h60
  text "X" at 12576.46,3568.96 h60
  text "GREEN" at 12694.46,3568.96 h60
  text "OTHER" at 13312.46,3568.96 h60
  text "SOLDER RESIST COLOR:" at 11488.68,3562.1 h60
  text "X" at 12576.46,3414.71 h60
  text "MATTE" at 12694.46,3414.71 h60
  text "SEMI-GLOSS" at 13312,3414.07 h60
  text "IMMERSION GOLD (ENIG)" at 12394.46,3241.94 h60
  text "ENEPIG" at 13732,3234.72 h60
  text "SURFACE FINISH:" at 11333.46,3233.72 h60
  text "X" at 12216.46,3233.72 h60
  text "IMM. TIN/SILVER OR EQUIV" at 11663,3096.4 h60
  text "OTHER" at 13094.46,3092.47 h60
  text "ARRAY/PANEL:" at 11333.46,2937.09 h60
  text "CUT AND TRIM PER M1 BOARD OUTLINE" at 12394.46,2928.87 h60
  text "N.C. ROUTE" at 12394.46,2792.9 h60
  text "X" at 13082.46,2792.9 h60
  text "V. SCORE" at 13260.46,2792.9 h60
  text "CERTIFICATION:" at 11333.46,2663.77 h60
  text "MATERIALS AND WORKMANSHIP FOR ALL PCBS" at 12058.46,2663.77 h60
  text "TO MEET OR EXCEED THE REQUIREMENTS OF:" at 12058.46,2569.71 h60
  text "X" at 11695.97,2441.08 h60
  text "ANSI IPC-A-600F CLASS ->" at 11823.96,2441.08 h60
  text "X" at 13471.97,2441.08 h60
  text "2" at 13581.96,2441.08 h60
  text "1" at 13266.96,2439.58 h60
  text "3" at 13935.96,2439.58 h60
  text "X" at 12507.97,2293.39 h60
  text "RoHS" at 12635.96,2293.39 h60
  text "OTHER" at 13280.36,2293.39 h60
  text "PER ORDER" at 13677.42,2293.39 h60
  text "ALL BOARDS MUST MEET OR EXCEED UL94-V0 REQUIREMENTS." at 11361,2139.57 h60
  text "PCB MUST BEAR THE UL94V-0 UL REGISTERED MATERIAL ID NUMBER" at 11361,2023.5 h60
  text "ADDITIONAL REQUIREMENTS:" at 11333.46,1854.08 h60
  text "MICROSECTION:" at 11408.23,1746.95 h60
  text "YES" at 12313.96,1746.95 h60
  text "REQUIRED" at 13175.46,1602.62 h60
  text "BARE BOARD ELEC. TEST:" at 11408.23,1599.76 h60
  text "NONE" at 12713.96,1599.76 h60
  text "X" at 13057.46,1599.76 h60
  text "PER ORDER" at 13767.46,1599.76 h60
  text "XX MIL VIAS REQUIRE NON-CONDUCTIVE FILL AND PLANARIZE" at 11576.38,1394.82 h59
  text "XX MIL VIAS REQUIRE CONDUCTIVE FILL AND PLANARIZE" at 11584.38,1290.84 h60
  text "OUTER XX MIL TRACES REQUIRE 50 OHM SINGLE-ENDED IMPEDANCE" at 11583.39,1127.46 h58
  text "LAYER 2 & 3 (INNER LAYERS) XX MIL WIDE, XX MIL SPACE / TRACES REQUIRE 100 OHM DIFFERENTIAL IMPEDANCE" at 11575.39,891.74 h60
  text ".Layer_Name" at 577,-858.49 h60
Mechanical 11:
  lines w10: -292,-930.17 6308,-930.17 ; -292,-726.83 6310,-726.83 ; -292,-523.5 -292,-1133.5 3713,-1133.5 6310,-1133.5 6310,-523.5 -291.5,-523.5 -291.5,-1133.5 1284,-1133.5 ; 2173,-1133.5 2173,-523.5 ; 3440,-726.83 3440,-523.5 ; 4280,-726.83 4280,-523.5 ; 4902,-1140 4902,-937.17
  text "ALL ARTWORK VIEWED FROM TOP SIDE" at -228.5,-655.67 h60
  text "BOARD #:" at 2248,-655.67 h60
  text ".PRJ_Number" at 2793.5,-655.67 h60
  text "REV:" at 3638,-655.67 h60
  text ".PCB_Rev" at 3929.5,-655.67 h60
  text "SVN REV:" at 4476,-655.67 h60
  text ".VersionControl_RevNumber" at 4982,-655.67 h60
  text "LAYER NAME =" at -228.5,-858.49 h60
  text "TID #:" at 2248,-859 h60
  text ".TID" at 2793.5,-859 h60
  text "PLOT NAME =" at -228.5,-1064.34 h60
  text ".plot_File_Name" at 577,-1064.34 h60
  text "GENERATED    :" at 2250,-1064.34 h60
  text ".Print_Date" at 3119.5,-1064.34 h60
  text ".Print_Time" at 3848.5,-1064.34 h60
  text "TEXAS INSTRUMENTS" at 5113,-1064.34 h60
Mechanical 12:
  drawing of 191 lines, arcs and shapes, not listed
  text "Layer" at 9797.84,7830 h60
  text "Name" at 10207.76,7830 h60
  text "Material" at 11137.5,7830 h60
  text "Thickness" at 11997.27,7830 h60
  text "Constant" at 12647.1,7830 h60
  text "Board Layer Stack" at 13216.96,7830 h60
  text "1" at 9797.84,7710 h60
  text "Top Overlay" at 10207.76,7710 h60
  text "2" at 9797.84,7590 h60
  text "Top Solder" at 10207.76,7590 h60
  text "Solder Resist" at 11137.5,7590 h60
  text "0.40mil" at 11997.27,7590 h60
  text "3.5" at 12647.1,7590 h60
  text "3" at 9797.84,7470 h60
  text "Top Layer" at 10207.76,7470 h60
  text "Copper" at 11137.5,7470 h60
  text "1.40mil" at 11997.27,7470 h60
  text "4" at 9797.84,7350 h60
  text "Dielectric1" at 10207.76,7350 h60
  text "FR-4" at 11137.5,7350 h60
  text "59.20mil" at 11997.27,7350 h60
  text "4.8" at 12647.1,7350 h60
  text "5" at 9797.84,7230 h60
  text "Bottom Layer" at 10207.76,7230 h60
  text "Copper" at 11137.5,7230 h60
  text "1.40mil" at 11997.27,7230 h60
  text "6" at 9797.84,7110 h60
  text "Bottom Solder" at 10207.76,7110 h60
  text "Solder Resist" at 11137.5,7110 h60
  text "0.40mil" at 11997.27,7110 h60
  text "3.5" at 12647.1,7110 h60
  text "7" at 9797.84,6990 h60
  text "Bottom Overlay" at 10207.76,6990 h60
  text ".Layer_Name" at 577,-858.49 h60
Mechanical 13:
  text ".Layer_Name" at 577,-858.49 h60
Mechanical 14:
  text ".Layer_Name" at 577,-858.49 h60
Mechanical 15:
  text ".Layer_Name" at 577,-858.49 h60
Top Component Center:
  text ".Layer_Name" at 577,-858.49 h60
Drill Drawing:
  text ".Layer_Name" at 577,-858.49 h60
Mechanical 17:
  text ".Layer_Name" at 577,-858.49 h60
Mechanical 18:
  text ".Layer_Name" at 577,-858.49 h60
Mechanical 19:
  text ".Layer_Name" at 577,-858.49 h60

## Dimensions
0,0 to 0,0 on Top 3D Body
0,-400 to 1000,-400 on Top 3D Body
0,0 to 0,4005 on Top 3D Body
